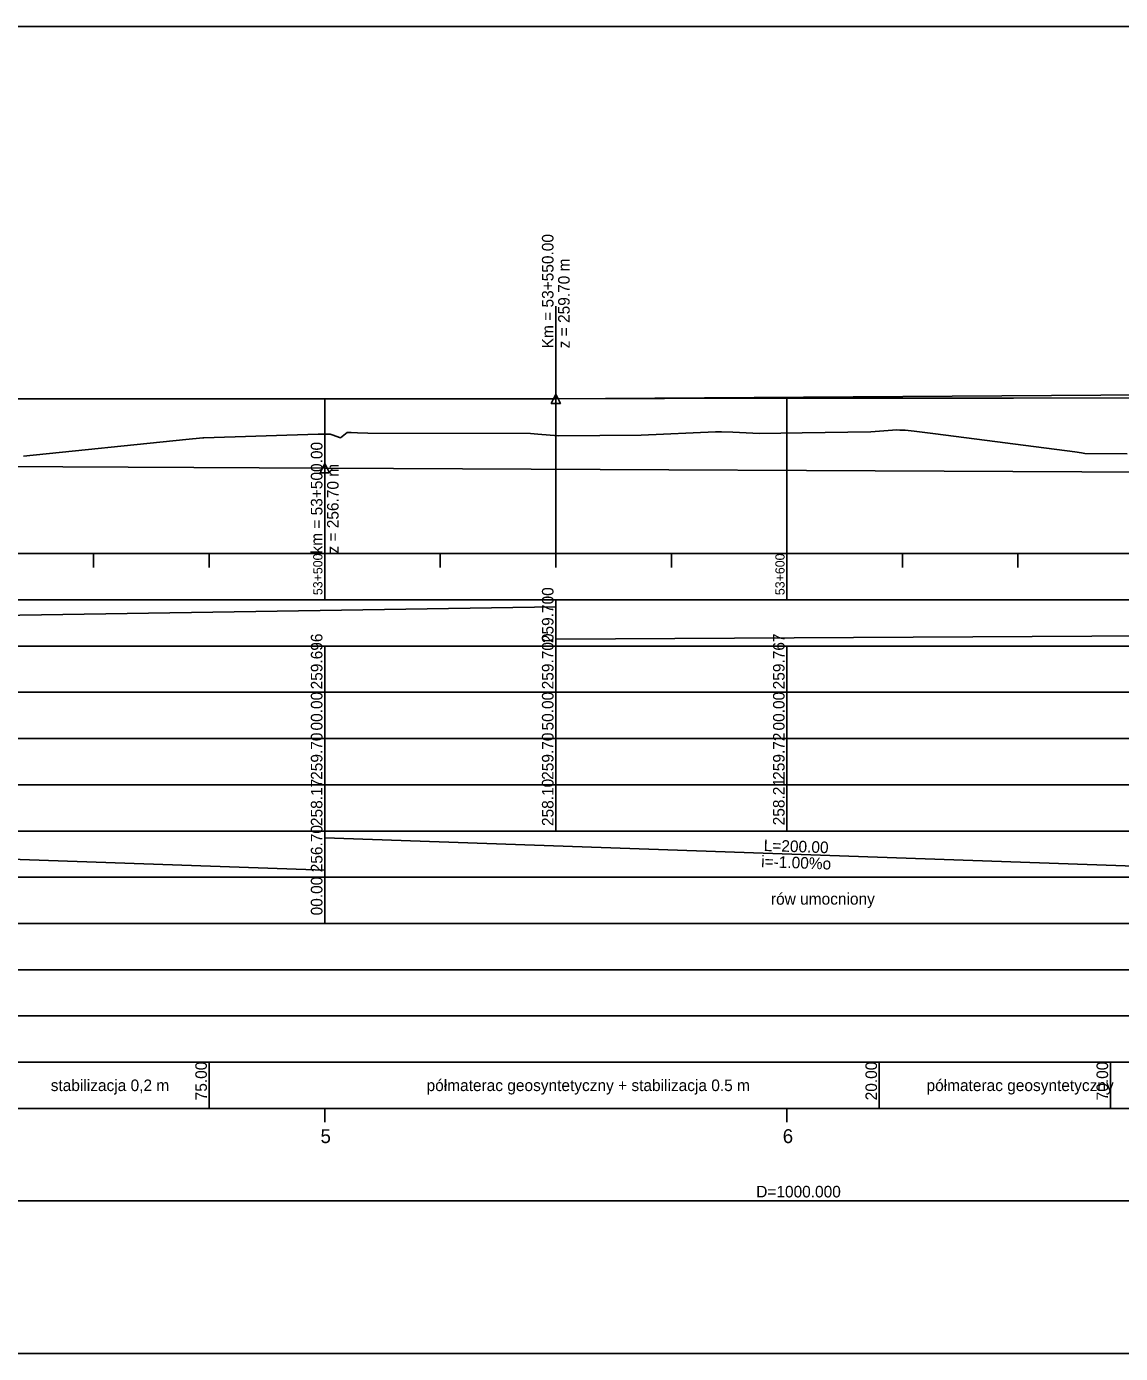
# Model space of a CAD drawing. Extents: x 6445630 to 6518227, y 5499240 to 5511716.
# Drawn here: x 6452666.7 to 6452903.4, y 5508418.3 to 5508705.3 of the extents above; entities that cross this region are included whole.
import ezdxf

# ---------------------------------------------------------------- set-up
doc = ezdxf.new("R2010")
doc.units = 0
for name, color, linetype in [('TOR_PROF-opisy pomocnicze', 7, 'Continuous'), ('TOR_PROF-rowy otwarte', 7, 'Continuous'), ('TOR_PROF-tabelka-geometria T1', 7, 'Continuous'), ('TOR_PROF-tabelka-kilometracja', 7, 'Continuous'), ('TOR_PROF-tabelka-odleglosci T1', 7, 'Continuous'), ('TOR_PROF-tabelka-pochylenia proj T1', 7, 'Continuous'), ('TOR_PROF-tabelka-rodzaj rowu T1', 7, 'Continuous'), ('TOR_PROF-tabelka-rowyT1', 7, 'Continuous'), ('TOR_PROF-tabelka-rurociagi T1', 7, 'Continuous'), ('TOR_PROF-tabelka-rzedne istn T1', 7, 'Continuous'), ('TOR_PROF-tabelka-rzedne proj T1', 7, 'Continuous'), ('TOR_PROF-tabelka-teren istniejacy T1', 7, 'Continuous'), ('TOR_PROF-tabelka-warstwa ochronna T1', 7, 'Continuous'), ('TOR_PROF-tor istniejacy T2', 7, 'Continuous'), ('TOR_PROF-tor projektowany', 7, 'Continuous'), ('TOR_PROF-uklad odniesienia', 7, 'Continuous'), ('TOR_PROF-warstwa ochronna', 7, 'Continuous'), ('TOR_RAMKI-dodatkowe3', 7, 'Continuous'), ('TOR_RAMKI-MASKA WYCIECIA', 7, 'Continuous')]:
    doc.layers.add(name, color=color, linetype=linetype)

msp = doc.modelspace()

# ---------------------------------------------------------------- linework, layer by layer
at = {"layer": 'TOR_PROF-opisy pomocnicze'}
for p, q in [((6452781.21, 5508624.79), (6452781.21, 5508644.79)), ((6452781.21, 5508624.79), (6452781.21, 5508644.79)), ((6452731.21, 5508609.79), (6452731.21, 5508591.29))]:
    msp.add_line(p, q, dxfattribs=at)
for points in [[(6452781.21, 5508625.79), (6452782.21, 5508623.79), (6452780.21, 5508623.79)], [(6452781.21, 5508625.79), (6452782.21, 5508623.79), (6452780.21, 5508623.79)], [(6452731.21, 5508610.79), (6452732.21, 5508608.79), (6452730.21, 5508608.79)]]:
    msp.add_lwpolyline(points, close=True, dxfattribs=at)
at = {"layer": 'TOR_PROF-rowy otwarte'}
for p, q in [((6452531.21, 5508610.79), (6452731.21, 5508609.79)), ((6452731.21, 5508609.79), (6452931.21, 5508608.79))]:
    msp.add_line(p, q, dxfattribs=at)
at = {"layer": 'TOR_PROF-tabelka-geometria T1'}
for points in [[(6452331.21, 5508451.29), (6453331.21, 5508451.29), (6453331.21, 5508448.62), (6453416.22, 5508448.62), (6453416.22, 5508451.29), (6453496.22, 5508451.29), (6453496.22, 5508453.96), (6453581.21, 5508453.96), (6453581.21, 5508451.29), (6457347.56, 5508451.29), (6457347.56, 5508448.62), (6457429.11, 5508448.62), (6457429.11, 5508451.29), (6457509.11, 5508451.29), (6457509.11, 5508453.96), (6457590.67, 5508453.96), (6457590.67, 5508451.29), (6459780.93, 5508451.29)], [(6452331.21, 5508451.29), (6462731.21, 5508451.29)]]:
    msp.add_lwpolyline(points, dxfattribs=at)
at = {"layer": 'TOR_PROF-tabelka-kilometracja'}
for points in [[(6452731.21, 5508468.29), (6452731.21, 5508471.29)], [(6452831.21, 5508468.29), (6452831.21, 5508471.29)]]:
    msp.add_lwpolyline(points, dxfattribs=at)
at = {"layer": 'TOR_PROF-tabelka-odleglosci T1'}
msp.add_lwpolyline([(6452331.21, 5508551.29), (6462731.21, 5508551.29), (6462731.21, 5508561.29), (6452331.21, 5508561.29)], close=True, dxfattribs=at)
for points in [[(6452731.21, 5508551.29), (6452731.21, 5508561.29)], [(6452781.21, 5508551.29), (6452781.21, 5508561.29)], [(6452831.21, 5508551.29), (6452831.21, 5508561.29)]]:
    msp.add_lwpolyline(points, dxfattribs=at)
at = {"layer": 'TOR_PROF-tabelka-pochylenia proj T1'}
msp.add_lwpolyline([(6452331.21, 5508571.29), (6462731.21, 5508571.29), (6462731.21, 5508581.29), (6452331.21, 5508581.29)], close=True, dxfattribs=at)
for points in [[(6452781.21, 5508571.29), (6452781.21, 5508581.29)], [(6452331.21, 5508572.79), (6452781.21, 5508579.79)], [(6452781.21, 5508572.79), (6454031.21, 5508579.79)]]:
    msp.add_lwpolyline(points, dxfattribs=at)
at = {"layer": 'TOR_PROF-tabelka-rodzaj rowu T1'}
for points in [[(6452331.21, 5508511.29), (6462731.21, 5508511.29), (6462731.21, 5508521.29), (6452331.21, 5508521.29)], [(6452331.21, 5508511.29), (6462731.21, 5508511.29), (6462731.21, 5508521.29), (6452331.21, 5508521.29)], [(6452331.21, 5508491.29), (6462731.21, 5508491.29), (6462731.21, 5508501.29), (6452331.21, 5508501.29)]]:
    msp.add_lwpolyline(points, close=True, dxfattribs=at)
msp.add_lwpolyline([(6452731.21, 5508511.29), (6452731.21, 5508521.29)], dxfattribs=at)
at = {"layer": 'TOR_PROF-tabelka-rowyT1'}
msp.add_lwpolyline([(6452331.21, 5508521.29), (6462731.21, 5508521.29), (6462731.21, 5508531.29), (6452331.21, 5508531.29)], close=True, dxfattribs=at)
msp.add_lwpolyline([(6452331.21, 5508521.29), (6462731.21, 5508521.29), (6462731.21, 5508531.29), (6452331.21, 5508531.29)], close=True, dxfattribs=at)
msp.add_lwpolyline([(6452331.21, 5508521.29), (6462731.21, 5508521.29), (6462731.21, 5508531.29), (6452331.21, 5508531.29)], close=True, dxfattribs=at)
for points in [[(6452531.21, 5508529.79), (6452731.21, 5508522.79)], [(6452731.21, 5508521.29), (6452731.21, 5508531.29)], [(6452731.21, 5508529.79), (6452931.21, 5508522.79)]]:
    msp.add_lwpolyline(points, dxfattribs=at)
at = {"layer": 'TOR_PROF-tabelka-rurociagi T1'}
msp.add_lwpolyline([(6452331.21, 5508501.29), (6462731.21, 5508501.29), (6462731.21, 5508511.29), (6452331.21, 5508511.29)], close=True, dxfattribs=at)
at = {"layer": 'TOR_PROF-tabelka-rzedne istn T1'}
msp.add_lwpolyline([(6452331.21, 5508541.29), (6462731.21, 5508541.29), (6462731.21, 5508551.29), (6452331.21, 5508551.29)], close=True, dxfattribs=at)
for points in [[(6452731.21, 5508541.29), (6452731.21, 5508551.29)], [(6452781.21, 5508541.29), (6452781.21, 5508551.29)], [(6452831.21, 5508541.29), (6452831.21, 5508551.29)], [(6452731.21, 5508531.29), (6452731.21, 5508541.29)], [(6452731.21, 5508531.29), (6452731.21, 5508541.29)], [(6452731.21, 5508531.29), (6452731.21, 5508541.29)], [(6452731.21, 5508531.29), (6452731.21, 5508541.29)], [(6452781.21, 5508531.29), (6452781.21, 5508541.29)], [(6452781.21, 5508531.29), (6452781.21, 5508541.29)], [(6452781.21, 5508531.29), (6452781.21, 5508541.29)], [(6452781.21, 5508531.29), (6452781.21, 5508541.29)], [(6452831.21, 5508531.29), (6452831.21, 5508541.29)], [(6452831.21, 5508531.29), (6452831.21, 5508541.29)], [(6452831.21, 5508531.29), (6452831.21, 5508541.29)], [(6452831.21, 5508531.29), (6452831.21, 5508541.29)]]:
    msp.add_lwpolyline(points, dxfattribs=at)
at = {"layer": 'TOR_PROF-tabelka-rzedne proj T1'}
msp.add_lwpolyline([(6452331.21, 5508561.29), (6462731.21, 5508561.29), (6462731.21, 5508571.29), (6452331.21, 5508571.29)], close=True, dxfattribs=at)
for points in [[(6452731.21, 5508561.29), (6452731.21, 5508571.29)], [(6452781.21, 5508561.29), (6452781.21, 5508571.29)], [(6452831.21, 5508561.29), (6452831.21, 5508571.29)]]:
    msp.add_lwpolyline(points, dxfattribs=at)
at = {"layer": 'TOR_PROF-tabelka-teren istniejacy T1'}
msp.add_lwpolyline([(6452331.21, 5508531.29), (6462731.21, 5508531.29), (6462731.21, 5508541.29), (6452331.21, 5508541.29)], close=True, dxfattribs=at)
msp.add_lwpolyline([(6452331.21, 5508531.29), (6462731.21, 5508531.29), (6462731.21, 5508541.29), (6452331.21, 5508541.29)], close=True, dxfattribs=at)
msp.add_lwpolyline([(6452331.21, 5508531.29), (6462731.21, 5508531.29), (6462731.21, 5508541.29), (6452331.21, 5508541.29)], close=True, dxfattribs=at)
msp.add_lwpolyline([(6452331.21, 5508531.29), (6462731.21, 5508531.29), (6462731.21, 5508541.29), (6452331.21, 5508541.29)], close=True, dxfattribs=at)
at = {"layer": 'TOR_PROF-tabelka-warstwa ochronna T1'}
msp.add_lwpolyline([(6452331.21, 5508481.29), (6462731.21, 5508481.29), (6462731.21, 5508491.29), (6452331.21, 5508491.29)], close=True, dxfattribs=at)
at = {"layer": 'TOR_PROF-tor istniejacy T2'}
msp.add_lwpolyline([(6453481.89, 5508627.69), (6453429.5, 5508627.34), (6453379.8, 5508626.79), (6453330.72, 5508626.39), (6453285.77, 5508625.99), (6453230.52, 5508625.79), (6453217.87, 5508625.74), (6453187.39, 5508625.69), (6453131.5, 5508625.54), (6453081.9, 5508625.39), (6453029.03, 5508625.29), (6453014.31, 5508625.29), (6452980.68, 5508625.04), (6452930.96, 5508624.99), (6452880.22, 5508624.89), (6452829.41, 5508624.89), (6452780.05, 5508624.79), (6452735.46, 5508624.79), (6452681.99, 5508624.74), (6452629.4, 5508624.69)], dxfattribs=at)
at = {"layer": 'TOR_PROF-tor projektowany'}
for p, q in [((6452781.21, 5508624.79), (6454031.21, 5508633.12)), ((6452781.21, 5508624.79), (6454031.21, 5508633.12)), ((6452331.21, 5508624.62), (6452781.21, 5508624.79)), ((6452331.21, 5508624.62), (6452781.21, 5508624.79))]:
    msp.add_line(p, q, dxfattribs=at)
for points in [[(6452731.21, 5508624.77), (6452731.21, 5508596.29), (6452731.21, 5508591.29), (6452731.21, 5508591.29)], [(6452731.21, 5508624.77), (6452731.21, 5508596.29), (6452731.21, 5508591.29), (6452731.21, 5508591.29)], [(6452781.21, 5508624.79), (6452781.21, 5508596.29), (6452781.21, 5508591.29), (6452781.21, 5508591.29)], [(6452781.21, 5508624.79), (6452781.21, 5508596.29), (6452781.21, 5508591.29), (6452781.21, 5508591.29)], [(6452781.21, 5508624.79), (6452781.21, 5508596.29), (6452781.21, 5508591.29), (6452781.21, 5508591.29)], [(6452781.21, 5508624.79), (6452781.21, 5508596.29), (6452781.21, 5508591.29), (6452781.21, 5508591.29)], [(6452831.21, 5508625.12), (6452831.21, 5508596.29), (6452831.21, 5508591.29), (6452831.21, 5508591.29)], [(6452831.21, 5508625.12), (6452831.21, 5508596.29), (6452831.21, 5508591.29), (6452831.21, 5508591.29)]]:
    msp.add_lwpolyline(points, dxfattribs=at)
at = {"layer": 'TOR_PROF-uklad odniesienia'}
for p, q in [((6452331.21, 5508591.29), (6462731.21, 5508591.29)), ((6452331.21, 5508591.29), (6462731.21, 5508591.29)), ((6452681.21, 5508588.29), (6452681.21, 5508591.29)), ((6452681.21, 5508588.29), (6452681.21, 5508591.29)), ((6452706.21, 5508588.29), (6452706.21, 5508591.29)), ((6452706.21, 5508588.29), (6452706.21, 5508591.29)), ((6452731.21, 5508581.29), (6452731.21, 5508591.29)), ((6452731.21, 5508581.29), (6452731.21, 5508591.29)), ((6452756.21, 5508588.29), (6452756.21, 5508591.29)), ((6452756.21, 5508588.29), (6452756.21, 5508591.29)), ((6452781.21, 5508588.29), (6452781.21, 5508591.29)), ((6452781.21, 5508588.29), (6452781.21, 5508591.29)), ((6452806.21, 5508588.29), (6452806.21, 5508591.29)), ((6452806.21, 5508588.29), (6452806.21, 5508591.29)), ((6452831.21, 5508581.29), (6452831.21, 5508591.29)), ((6452831.21, 5508581.29), (6452831.21, 5508591.29)), ((6452856.21, 5508588.29), (6452856.21, 5508591.29)), ((6452856.21, 5508588.29), (6452856.21, 5508591.29)), ((6452881.21, 5508588.29), (6452881.21, 5508591.29)), ((6452881.21, 5508588.29), (6452881.21, 5508591.29))]:
    msp.add_line(p, q, dxfattribs=at)
at = {"layer": 'TOR_PROF-warstwa ochronna'}
msp.add_lwpolyline([(6452331.21, 5508471.29), (6462731.21, 5508471.29), (6462731.21, 5508481.29), (6452331.21, 5508481.29)], close=True, dxfattribs=at)
for points in [[(6452706.21, 5508471.29), (6452706.21, 5508481.29)], [(6452851.21, 5508471.29), (6452851.21, 5508481.29)], [(6452901.21, 5508471.29), (6452901.21, 5508481.29)]]:
    msp.add_lwpolyline(points, dxfattribs=at)
at = {"layer": 'TOR_RAMKI-dodatkowe3'}
for p, q in [((6452849.35, 5508617.66), (6452854.97, 5508618.05)), ((6452854.97, 5508618.05), (6452855.67, 5508618.01)), ((6452855.67, 5508618.01), (6452856.78, 5508617.96)), ((6452856.78, 5508617.96), (6452858.77, 5508617.79)), ((6452858.77, 5508617.79), (6452863.38, 5508617.21)), ((6452666, 5508612.38), (6452701.13, 5508615.95)), ((6452701.13, 5508615.95), (6452704.83, 5508616.34)), ((6452704.83, 5508616.34), (6452704.89, 5508616.33)), ((6452704.89, 5508616.33), (6452705.02, 5508616.33)), ((6452705.02, 5508616.33), (6452729.79, 5508617.09)), ((6452729.79, 5508617.09), (6452732.37, 5508617.15)), ((6452732.37, 5508617.15), (6452732.82, 5508616.99)), ((6452732.82, 5508616.99), (6452734.62, 5508616.35)), ((6452734.62, 5508616.35), (6452736.1, 5508617.47)), ((6452736.1, 5508617.47), (6452736.94, 5508617.5)), ((6452736.94, 5508617.5), (6452738.28, 5508617.42)), ((6452738.28, 5508617.42), (6452740.53, 5508617.36)), ((6452740.53, 5508617.36), (6452775.75, 5508617.26)), ((6452775.75, 5508617.26), (6452777.35, 5508617.16)), ((6452777.35, 5508617.16), (6452781.81, 5508616.73)), ((6452781.81, 5508616.73), (6452799.65, 5508616.89)), ((6452799.65, 5508616.89), (6452815.73, 5508617.62)), ((6452815.73, 5508617.62), (6452817.06, 5508617.6)), ((6452817.06, 5508617.6), (6452819.49, 5508617.55)), ((6452819.49, 5508617.55), (6452825.26, 5508617.26)), ((6452825.26, 5508617.26), (6452834.55, 5508617.41)), ((6452834.55, 5508617.41), (6452849.35, 5508617.66)), ((6452863.38, 5508617.21), (6452893.49, 5508613.27)), ((6452893.49, 5508613.27), (6452894.95, 5508613.06)), ((6452894.95, 5508613.06), (6452895.65, 5508612.96)), ((6452895.65, 5508612.96), (6452904.86, 5508612.86))]:
    msp.add_line(p, q, dxfattribs=at)
at = {"layer": 'TOR_RAMKI-MASKA WYCIECIA'}
msp.add_lwpolyline([(6452266.8, 5508418.29), (6454296.8, 5508418.29), (6454296.8, 5508705.29), (6452266.8, 5508705.29)], close=True, dxfattribs=at)

# ---------------------------------------------------------------- texts
at = {"layer": 'TOR_PROF-opisy pomocnicze'}
for s, p in [('Km = 53+550.00', (6452780.71, 5508635.69)), ('Km = 53+550.00', (6452780.71, 5508635.69)), ('z = 259.70 m', (6452784.21, 5508635.69)), ('z = 259.70 m', (6452784.21, 5508635.69)), ('km = 53+500.00', (6452730.71, 5508591.29)), ('z = 256.70 m', (6452734.21, 5508591.29))]:
    msp.add_text(s, height=2.5, rotation=90, dxfattribs=at).set_placement(p)
at = {"layer": 'TOR_PROF-tabelka-geometria T1'}
msp.add_text('D=1000.000', height=2.5, dxfattribs=at).set_placement((6452824.57, 5508452.04))
at = {"layer": 'TOR_PROF-tabelka-kilometracja'}
for s, p in [('5', (6452730.31, 5508463.79)), ('6', (6452830.32, 5508463.79))]:
    msp.add_text(s, height=3, dxfattribs=at).set_placement(p)
at = {"layer": 'TOR_PROF-tabelka-odleglosci T1'}
for s, p in [('00.00', (6452730.71, 5508553.03)), ('50.00', (6452780.71, 5508553.03)), ('00.00', (6452830.71, 5508553.03))]:
    msp.add_text(s, height=2.5, rotation=90, dxfattribs=at).set_placement(p)
at = {"layer": 'TOR_PROF-tabelka-pochylenia proj T1'}
msp.add_text('259.700', height=2.5, rotation=90, dxfattribs=at).set_placement((6452780.71, 5508571.93))
at = {"layer": 'TOR_PROF-tabelka-rodzaj rowu T1'}
msp.add_text('00.00', height=2.5, rotation=90, dxfattribs=at).set_placement((6452730.71, 5508513.04))
at = {"layer": 'TOR_PROF-tabelka-rowyT1'}
for s, rotation, p in [('256.70', 90, (6452730.71, 5508522.36)), ('L=200.00', 357.9955, (6452826.16, 5508526.97)), ('i=-1.00%o', 357.9955, (6452825.61, 5508523.48)), ('rów umocniony', 0.087, (6452827.76, 5508515.35))]:
    msp.add_text(s, height=2.5, rotation=rotation, dxfattribs=at).set_placement(p)
at = {"layer": 'TOR_PROF-tabelka-rzedne istn T1'}
for s, p in [('259.70', (6452730.71, 5508542.36)), ('259.70', (6452780.71, 5508542.36)), ('259.72', (6452830.71, 5508542.36)), ('258.17', (6452730.71, 5508532.36)), ('258.10', (6452780.71, 5508532.36)), ('258.21', (6452830.71, 5508532.52))]:
    msp.add_text(s, height=2.5, rotation=90, dxfattribs=at).set_placement(p)
at = {"layer": 'TOR_PROF-tabelka-rzedne proj T1'}
for s, p in [('259.696', (6452730.71, 5508561.92)), ('259.700', (6452780.71, 5508561.93)), ('259.767', (6452830.71, 5508561.93))]:
    msp.add_text(s, height=2.5, rotation=90, dxfattribs=at).set_placement(p)
at = {"layer": 'TOR_PROF-uklad odniesienia'}
for s, p in [('53+500', (6452730.71, 5508582.31)), ('53+500', (6452730.71, 5508582.31)), ('53+600', (6452830.71, 5508582.31)), ('53+600', (6452830.71, 5508582.31))]:
    msp.add_text(s, height=2, rotation=90, dxfattribs=at).set_placement(p)
at = {"layer": 'TOR_PROF-warstwa ochronna'}
for s, rotation, p in [('75.00', 90, (6452705.71, 5508473.04)), ('20.00', 90, (6452850.71, 5508473.04)), ('70.00', 90, (6452900.71, 5508473.04)), ('stabilizacja 0,2 m', 360, (6452671.92, 5508475.04)), ('półmaterac geosyntetyczny + stabilizacja 0.5 m', 360, (6452753.25, 5508475.04)), ('półmaterac geosyntetyczny', 360, (6452861.42, 5508475.04))]:
    msp.add_text(s, height=2.5, rotation=rotation, dxfattribs=at).set_placement(p)

doc.saveas('drawing.dxf')
